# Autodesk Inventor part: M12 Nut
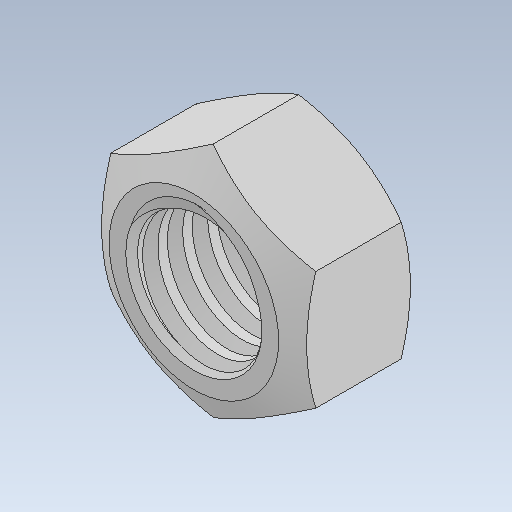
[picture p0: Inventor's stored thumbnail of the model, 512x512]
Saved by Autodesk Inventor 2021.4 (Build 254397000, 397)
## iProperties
Created: 2017-11
Part Number: M12 Nut
Material: Ogólny
Document SubType Name: Modeling
Designer: user
Density: 1 g/cm^3
Appearance: Domyślna
Author: user
Revision Number: ÈÎºÎ
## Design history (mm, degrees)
feature "ÇÐ³ý-É¨Ãè2"
node "Bryła1"
